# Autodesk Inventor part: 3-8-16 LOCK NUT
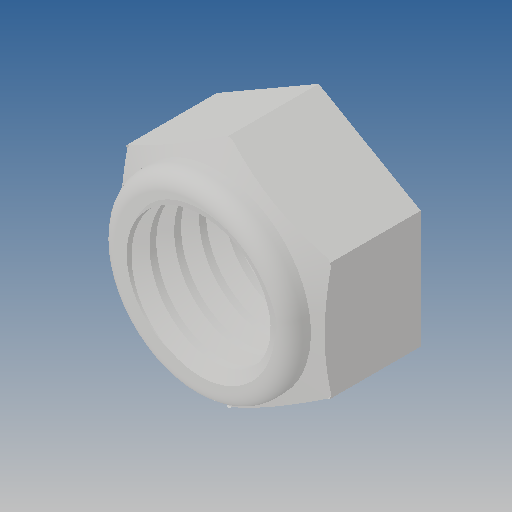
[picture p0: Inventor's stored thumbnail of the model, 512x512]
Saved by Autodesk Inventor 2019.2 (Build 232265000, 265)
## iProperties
Created: 2012-09
Part Number: 3-8-16 LOCK NUT
Material: Ogólny
Document SubType Name: Modeling
Designer: CADENGINEERING4
Density: 1 g/cm^3
Appearance: Domyślna
Author: CADENGINEERING4
Revision Number: ÈÎºÎ
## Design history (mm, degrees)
feature "ÇÐ³ý-É¨Ãè1"
node "Bryła1"
